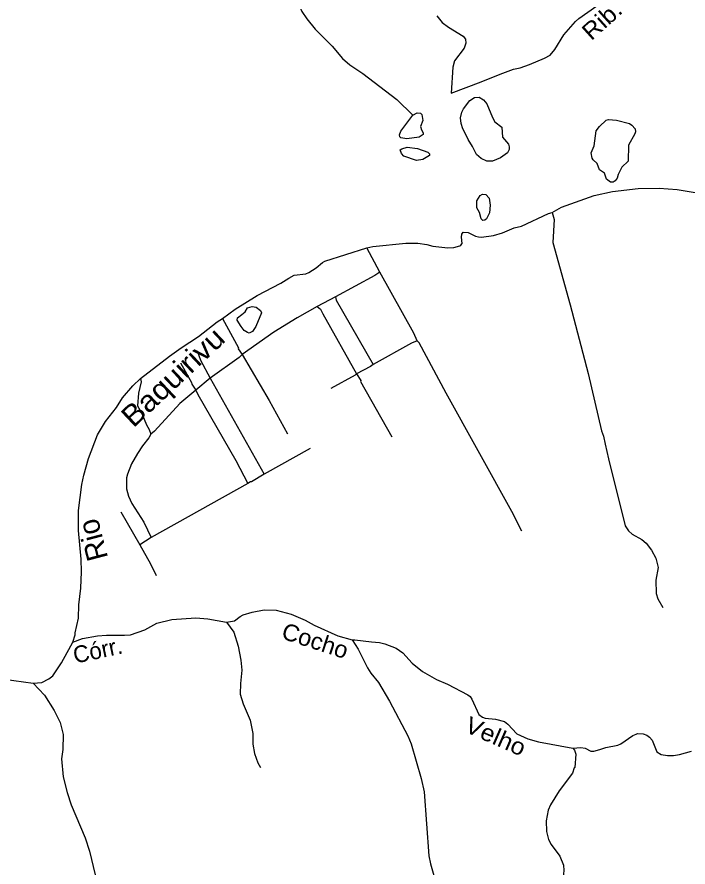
# Model space of a CAD drawing. Extents: x 346.5 to 372.4, y 7400.3 to 7428.2.
# Drawn here: x 350.815 to 354.02, y 7406.713 to 7410.774 of the extents above; entities that cross this region are included whole.
import ezdxf
from ezdxf.enums import TextEntityAlignment as Align

# ---------------------------------------------------------------- set-up
doc = ezdxf.new("R2010")
doc.units = 0
doc.header["$LTSCALE"] = 0.032
for name, color, linetype, lineweight in [('1', 7, 'Continuous', 25), ('2', 7, 'Continuous', 25), ('7', 7, 'Continuous', 25)]:
    doc.layers.add(name, color=color, linetype=linetype, lineweight=lineweight)
doc.layers.add('61', color=7, linetype='Continuous')

msp = doc.modelspace()

# ---------------------------------------------------------------- linework, layer by layer
at = {"layer": '1'}
for p, q in [((352.2152, 7408.7124), (351.9964, 7408.5905)), ((351.3115, 7408.4095), (351.4014, 7408.2516))]:
    msp.add_line(p, q, dxfattribs=at)
for points in [[(353.3719, 7409.84), (353.3804, 7409.8066), (353.374, 7409.6966), (353.4577, 7409.3985), (353.5437, 7409.0702), (353.6075, 7408.796), (353.6171, 7408.7705), (353.625, 7408.7323), (353.641, 7408.6637), (353.7207, 7408.3434), (353.7358, 7408.3187), (353.7541, 7408.3027), (353.8004, 7408.278), (353.8203, 7408.2597), (353.8458, 7408.2262), (353.8657, 7408.1888), (353.8769, 7408.1441), (353.8657, 7408.0836), (353.8673, 7408.0198), (353.8761, 7407.9943), (353.9, 7407.9521)], [(352.7264, 7409.2274), (352.7101, 7409.2631), (352.5477, 7409.5547), (352.4858, 7409.6704)], [(352.5477, 7409.5547), (352.5237, 7409.5388), (352.3372, 7409.4376), (352.2495, 7409.3905)], [(352.3372, 7409.4376), (352.3404, 7409.4216), (352.516, 7409.1136)], [(352.2495, 7409.3905), (352.1531, 7409.3371), (352.0423, 7409.2678), (351.8909, 7409.1608)], [(352.2495, 7409.3905), (352.2655, 7409.3786), (352.2758, 7409.3555), (352.4371, 7409.0686)], [(351.7965, 7409.3331), (351.8733, 7409.1937), (351.8711, 7409.1888), (351.8909, 7409.1608)], [(352.7264, 7409.2274), (352.699, 7409.2152), (352.516, 7409.1136)], [(353.2258, 7408.3171), (353.1795, 7408.4119), (352.8647, 7408.9762), (352.7356, 7409.2176), (352.7264, 7409.2274)], [(351.6757, 7409.1794), (351.6913, 7409.134), (351.7385, 7409.0484), (351.9964, 7408.5905)], [(351.8909, 7409.1608), (351.8767, 7409.1466), (351.7385, 7409.0484), (351.6688, 7408.9916)], [(351.8909, 7409.1608), (352.02, 7408.9411), (352.1077, 7408.7825)], [(351.596, 7409.122), (351.6494, 7409.0279), (351.6501, 7409.0201), (351.6688, 7408.9916)], [(352.516, 7409.1136), (352.5029, 7409.1036), (352.4371, 7409.0686)], [(352.4371, 7409.0686), (352.4312, 7409.0622), (352.3141, 7408.9985)], [(352.4371, 7409.0686), (352.458, 7409.0368), (352.4567, 7409.0319), (352.605, 7408.7681)], [(351.4055, 7409.0461), (351.4077, 7409.0312), (351.3952, 7408.9762), (351.3916, 7408.9163), (351.4111, 7408.8794), (351.4334, 7408.8247), (351.4473, 7408.8033), (351.4547, 7408.7801)], [(351.6688, 7408.9916), (351.5936, 7408.9267), (351.4724, 7408.795), (351.4547, 7408.7801)], [(351.6688, 7408.9916), (351.6784, 7408.9697), (351.8606, 7408.6558), (351.9185, 7408.5457)], [(351.4547, 7408.7801), (351.4454, 7408.763), (351.4151, 7408.7251), (351.3912, 7408.6877), (351.3625, 7408.6398), (351.3426, 7408.5904), (351.3386, 7408.5729), (351.3378, 7408.5203), (351.3474, 7408.4852), (351.3641, 7408.4502), (351.4207, 7408.3609), (351.4555, 7408.2865)], [(351.9964, 7408.5905), (351.9355, 7408.553), (351.9306, 7408.5535), (351.9185, 7408.5457), (351.4555, 7408.2865), (351.4014, 7408.2516)], [(351.4014, 7408.2516), (351.4526, 7408.1617), (351.4797, 7408.1051)]]:
    msp.add_lwpolyline(points, dxfattribs=at)
at = {"layer": '2'}
for points in [[(352.9597, 7410.2125), (352.9448, 7410.239), (352.9373, 7410.2656), (352.9341, 7410.2926), (352.9403, 7410.3192), (352.9479, 7410.3342), (352.9778, 7410.3753), (353.0007, 7410.3893), (353.0228, 7410.3902), (353.0435, 7410.3783), (353.0593, 7410.3581), (353.0861, 7410.2934), (353.0973, 7410.2733), (353.1302, 7410.2478), (353.134, 7410.1992), (353.162, 7410.1657), (353.1664, 7410.1538), (353.1661, 7410.1409), (353.1576, 7410.1248), (353.125, 7410.1013), (353.0857, 7410.0849), (353.059, 7410.0853), (353.0328, 7410.0983), (353.0097, 7410.1163), (352.991, 7410.1552), (352.9696, 7410.189)], [(352.7056, 7410.3052), (352.7265, 7410.3152), (352.7429, 7410.3135), (352.7492, 7410.308), (352.7536, 7410.2793), (352.7429, 7410.2502), (352.7468, 7410.2353), (352.756, 7410.2204), (352.7549, 7410.2117), (352.7356, 7410.1994), (352.6773, 7410.1916), (352.6484, 7410.1964), (352.6434, 7410.2016), (352.642, 7410.2106), (352.6487, 7410.228)], [(353.5815, 7410.2295), (353.5969, 7410.2511), (353.63, 7410.2808), (353.6402, 7410.2845), (353.6793, 7410.2803), (353.7402, 7410.265), (353.7524, 7410.2563), (353.7672, 7410.2389), (353.769, 7410.2252), (353.7667, 7410.2153), (353.7358, 7410.1609), (353.7344, 7410.0851), (353.7033, 7410.0563), (353.6862, 7410.021), (353.6819, 7410.003), (353.672, 7409.9906), (353.6621, 7409.9844), (353.6499, 7409.9851), (353.6315, 7409.9994), (353.6211, 7410.0279), (353.5975, 7410.0435), (353.5858, 7410.0736), (353.5668, 7410.0908), (353.5621, 7410.0987), (353.5578, 7410.1248), (353.5724, 7410.1577)], [(352.7856, 7410.1121), (352.7533, 7410.0927), (352.7237, 7410.0882), (352.6634, 7410.1092), (352.6511, 7410.1223), (352.6459, 7410.1383), (352.6535, 7410.144), (352.6786, 7410.1515), (352.7279, 7410.1449), (352.7769, 7410.1273), (352.7847, 7410.1203)], [(353.0705, 7409.9086), (353.0747, 7409.8744), (353.0721, 7409.838), (353.057, 7409.8089), (353.0491, 7409.8033), (353.04, 7409.8019), (353.032, 7409.8094), (353.0236, 7409.8394), (353.0122, 7409.8627), (353.0112, 7409.8955), (353.0282, 7409.9203), (353.0386, 7409.9271), (353.0545, 7409.9256)], [(351.8891, 7409.3521), (351.9047, 7409.3659), (351.917, 7409.3838), (351.9392, 7409.3914), (351.9577, 7409.3877), (351.9786, 7409.3718), (351.9836, 7409.3603), (351.956, 7409.2949), (351.9399, 7409.2714), (351.9238, 7409.2633), (351.9156, 7409.2657), (351.9009, 7409.2768), (351.8862, 7409.2945), (351.8676, 7409.3257), (351.8682, 7409.3371)]]:
    msp.add_lwpolyline(points, close=True, dxfattribs=at)
at = {"layer": '7'}
for points in [[(352.1332, 7410.9024), (352.1754, 7410.7996), (352.1993, 7410.7653), (352.2391, 7410.7151), (352.3212, 7410.6338), (352.3706, 7410.5756), (352.4049, 7410.5445), (352.4663, 7410.5039), (352.6297, 7410.3788), (352.7056, 7410.3052)], [(352.8201, 7410.7788), (352.8464, 7410.747), (352.8767, 7410.7246), (352.9461, 7410.6816), (352.9572, 7410.6673), (352.9588, 7410.6481), (352.9508, 7410.625), (352.9046, 7410.5645), (352.8974, 7410.5334), (352.8887, 7410.4098), (353.0321, 7410.464), (353.123, 7410.4999), (353.1867, 7410.5246), (353.2186, 7410.5302), (353.2632, 7410.5469), (353.335, 7410.5764), (353.3621, 7410.5907), (353.3844, 7410.6179), (353.4274, 7410.6888), (353.4824, 7410.7525), (353.4983, 7410.7669), (353.5852, 7410.8266)], [(351.082, 7407.7869), (351.0939, 7407.823), (351.0939, 7407.8325), (351.1091, 7407.9019), (351.1107, 7407.9656), (351.1194, 7408.0453), (351.1226, 7408.1234), (351.1218, 7408.184), (351.1083, 7408.3211), (351.1083, 7408.4167), (351.1242, 7408.541), (351.1346, 7408.5856), (351.1569, 7408.6653), (351.1991, 7408.7769), (351.2374, 7408.8407), (351.29, 7408.9076), (351.3187, 7408.9538), (351.3681, 7409.0112), (351.4055, 7409.0461), (351.5434, 7409.1539), (351.6, 7409.1937), (351.6821, 7409.2479), (351.7714, 7409.318), (351.7965, 7409.3331), (351.8566, 7409.3778), (351.9626, 7409.4431), (352.075, 7409.5029), (352.1132, 7409.5268), (352.1395, 7409.5396), (352.1953, 7409.5467), (352.2097, 7409.5523), (352.2439, 7409.5746), (352.2742, 7409.6009), (352.2862, 7409.6065), (352.4858, 7409.6704), (352.5141, 7409.6774), (352.6719, 7409.6934), (352.7293, 7409.6926), (352.7723, 7409.6862), (352.801, 7409.6782), (352.8727, 7409.6711), (352.9014, 7409.6719), (352.9301, 7409.6806), (352.9357, 7409.683), (352.9413, 7409.691), (352.9389, 7409.7221), (352.9397, 7409.7364), (352.9468, 7409.746), (352.97, 7409.7436), (353.005, 7409.7261), (353.0194, 7409.7237), (353.0337, 7409.7221), (353.0911, 7409.7292), (353.1341, 7409.7428), (353.1899, 7409.7659), (353.225, 7409.7747), (353.3541, 7409.8344), (353.3719, 7409.84), (353.4162, 7409.8655), (353.5725, 7409.9205), (353.6601, 7409.9396), (353.7828, 7409.954), (353.8817, 7409.9564), (353.9677, 7409.95), (354.0729, 7409.9317)], [(351.8161, 7407.8826), (351.8542, 7407.8891), (351.8813, 7407.9098), (351.8957, 7407.917), (351.9387, 7407.9313), (351.9961, 7407.9409), (352.0535, 7407.9401), (352.1252, 7407.921), (352.1913, 7407.8931), (352.2352, 7407.8692), (352.3483, 7407.8174), (352.4162, 7407.7977)], [(351.082, 7407.7869), (351.1274, 7407.8046), (351.1991, 7407.8174), (351.2422, 7407.8214), (351.3283, 7407.8206), (351.3569, 7407.823), (351.4255, 7407.8461), (351.4829, 7407.8787), (351.5546, 7407.8947), (351.6693, 7407.9034), (351.7267, 7407.8979), (351.8161, 7407.8826)], [(351.8161, 7407.8826), (351.851, 7407.8349), (351.8718, 7407.768), (351.8837, 7407.701), (351.8885, 7407.6532), (351.8821, 7407.5895), (351.8813, 7407.5385), (351.8949, 7407.4922), (351.9283, 7407.4141), (351.9411, 7407.3504), (351.9419, 7407.2994), (351.9491, 7407.2547), (351.965, 7407.2101), (351.9778, 7407.1886)], [(352.4162, 7407.7977), (352.4286, 7407.7977), (352.5077, 7407.7895), (352.546, 7407.7863), (352.5715, 7407.7799), (352.6257, 7407.7584), (352.6575, 7407.7369), (352.7022, 7407.6867), (352.7516, 7407.6468), (352.8185, 7407.6086), (352.8711, 7407.5871), (352.9692, 7407.5361), (352.9795, 7407.5273), (352.9875, 7407.5146), (353.0217, 7407.442), (353.0385, 7407.4293), (353.0512, 7407.4237), (353.1007, 7407.4197), (353.1429, 7407.4077), (353.1596, 7407.3958), (353.2027, 7407.3488), (353.2553, 7407.3249), (353.3063, 7407.3113), (353.4705, 7407.2813)], [(352.4162, 7407.7977), (352.444, 7407.7536), (352.4886, 7407.6644), (352.5045, 7407.6389), (352.5412, 7407.5942), (352.5946, 7407.505), (352.6814, 7407.3392), (352.6982, 7407.301), (352.746, 7407.1352), (352.7595, 7407.0715), (352.7827, 7406.767), (352.7906, 7406.7288), (352.8265, 7406.6013), (352.8273, 7406.5247), (352.8217, 7406.3096), (352.7914, 7406.1151), (352.7883, 7405.9756)], [(350.893, 7407.5913), (350.9333, 7407.595), (350.9672, 7407.6118), (350.9864, 7407.6261), (351.0286, 7407.6891), (351.0731, 7407.769), (351.082, 7407.7869)], [(350.619, 7407.655), (350.6724, 7407.6269), (350.7066, 7407.6173), (350.893, 7407.5913)], [(350.893, 7407.5913), (350.9473, 7407.5337), (350.9935, 7407.4604), (351.0222, 7407.403), (351.0366, 7407.3456), (351.035, 7407.2739), (351.0286, 7407.2292), (351.0358, 7407.1432), (351.0549, 7407.0683), (351.074, 7407.0109), (351.141, 7406.8531), (351.1609, 7406.7893), (351.1894, 7406.6762), (351.1956, 7406.6645)], [(353.4705, 7407.2813), (353.5087, 7407.2842), (353.5286, 7407.2802), (353.5565, 7407.2659), (353.5709, 7407.2659), (353.5995, 7407.2739), (353.6282, 7407.2834), (353.6856, 7407.2954), (353.7, 7407.301), (353.7573, 7407.3408), (353.7733, 7407.348), (353.7788, 7407.3504), (353.8052, 7407.3488), (353.8235, 7407.3432), (353.837, 7407.3329), (353.8482, 7407.3185), (353.8713, 7407.2635), (353.8912, 7407.2507), (353.9215, 7407.2452), (353.9502, 7407.246), (353.9789, 7407.2507), (354.0363, 7407.2667)], [(353.4705, 7407.2813), (353.4784, 7407.2715), (353.484, 7407.2516), (353.48, 7407.1886), (353.4768, 7407.1862), (353.4688, 7407.1615), (353.4043, 7407.077), (353.3628, 7407.0109), (353.3517, 7406.9854), (353.3429, 7406.9344), (353.3437, 7406.8834), (353.3533, 7406.8451), (353.3668, 7406.8212), (353.4083, 7406.7646), (353.4258, 7406.7224), (353.4266, 7406.6969), (353.421, 7406.6331), (353.4003, 7406.5056), (353.4083, 7406.4674), (353.4216, 7406.4405), (353.423, 7406.4337)]]:
    msp.add_lwpolyline(points, dxfattribs=at)

# ---------------------------------------------------------------- texts
at = {"layer": '61'}
for s, height, rotation, width, p in [('Rib.', 0.08, 41.922, 1.1, (353.6358, 7410.7276)), ('Baquirivu', 0.1, 43.261, 1.1, (351.5941, 7409.0178)), ('Cocho', 0.08, 341.99, 1.05, (352.2273, 7407.7562)), ('Velho', 0.08, 336.286, 1.1, (353.0857, 7407.3011))]:
    msp.add_text(s, height=height, rotation=rotation, dxfattribs=dict(at, width=width)).set_placement(p, align=Align.CENTER)
for s, height, rotation, p in [('Rio', 0.1, 104.708, (351.2255, 7408.2878)), ('Córr.', 0.08, 12.093, (351.209, 7407.7094))]:
    msp.add_text(s, height=height, rotation=rotation, dxfattribs=at).set_placement(p, align=Align.CENTER)

doc.saveas('drawing.dxf')
